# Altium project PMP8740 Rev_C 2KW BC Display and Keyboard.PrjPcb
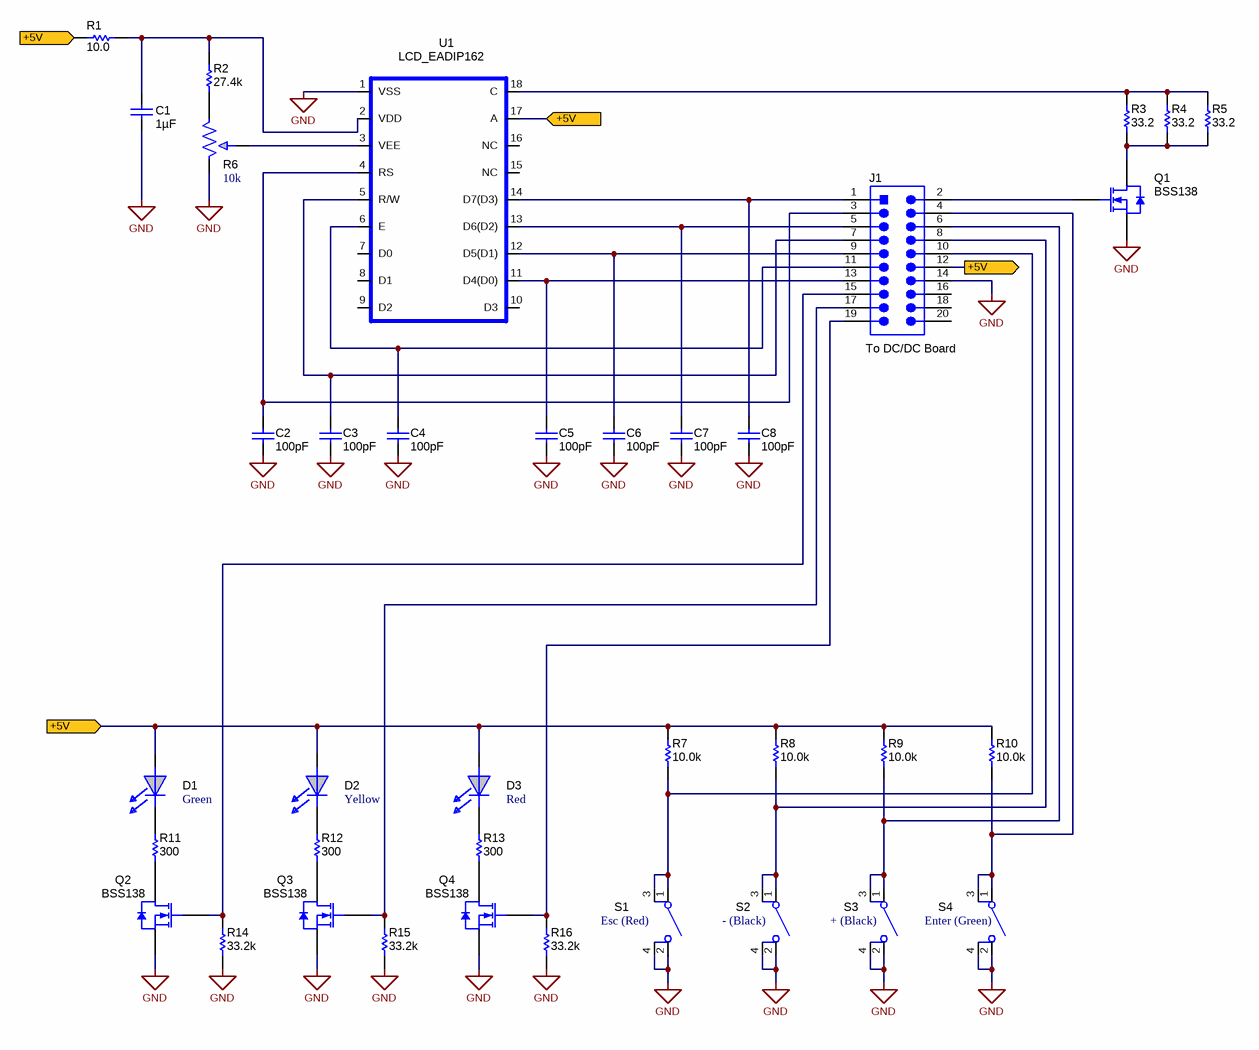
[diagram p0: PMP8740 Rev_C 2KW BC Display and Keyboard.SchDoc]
CopyrightYear: 2013; PCB_Layout: R. Scibilia; PCB_Rev: A; PRJ_Customer: Public Release; PRJ_Engineer: R. Scibilia; PRJ_Number: PMP8740; PRJ_Title: 1.44KW Battery Charger; SCH_Rev: A; TechSupport: http://www.ti.com/support
1 sheet, 37 parts. Net scope: flat (ports and power ports of the same name join across sheets).
Board file: PMP8740 Rev_C 2KW BC Display and Keyboard PCB.PcbDoc

## Sheet PMP8740 Rev_C 2KW BC Display and Keyboard.SchDoc: LCD Display
size 431 x 279 mm; Date: Not shown in title block; ApprovedBy: Not shown in title block; CheckedBy: Not shown in title block; Author: Not shown in title block; CompanyName: Not shown in title block; DrawnBy: R. Scibilia; Engineer: Not shown in title block; Organization: Not shown in title block; Address1: Not shown in title block; Address2: Not shown in title block; Address3: Not shown in title block; Address4: Not shown in title block; DocumentNumber: 1; Revision: Use project parameter SCH_Rev; SheetNumber: 1; SheetTotal: 1; PageSetup: Record=PageOptions|CenterHorizontal=True|CenterVertical=True|PrintScale=1.00|XCorrection=1.00|YCorrection=1.00|PrintKind=0|BorderSize=5000000|LeftOffset=0|BottomOffset=0|Orientation=2|PaperLength=1000|PaperWidth=1000|Scale=100|PaperSource=15|PrintQuality=600|MediaType=1|DitherType=10|PaperKind=Letter|PrintScaleMode=1

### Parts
C1  ValueDisplayed: 1µF  [0603]  (hidden comment: C1608X7R1E105K080AB)
C2  ValueDisplayed: 100pF  [0603]  (hidden comment: C1608C0G1H101J)
C3  ValueDisplayed: 100pF  [0603]  (hidden comment: C1608C0G1H101J)
C4  ValueDisplayed: 100pF  [0603]  (hidden comment: C1608C0G1H101J)
C5  ValueDisplayed: 100pF  [0603]  (hidden comment: C1608C0G1H101J)
C6  ValueDisplayed: 100pF  [0603]  (hidden comment: C1608C0G1H101J)
C7  ValueDisplayed: 100pF  [0603]  (hidden comment: C1608C0G1H101J)
C8  ValueDisplayed: 100pF  [0603]  (hidden comment: C1608C0G1H101J)
D1  value Green  [D_LED_T1-3/4]  (hidden comment: D_LED_HLMP-ED80)
D2  value Yellow  [D_LED_T1-3/4]  (hidden comment: D_LED_HLMP-ED80)
D3  value Red  [D_LED_T1-3/4]  (hidden comment: D_LED_HLMP-ED80)
J1  66506-072LF  [CONN_66506-072LF]  (value not drawn)
Q1  BSS138  [SOT-23]
Q2  BSS138  [SOT-23]
Q3  BSS138  [SOT-23]
Q4  BSS138  [SOT-23]
R1  value 10.0  [0603]  (hidden comment: CRCW060310R0FKEA)
R2  value 27.4k  [0603]  (hidden comment: CRCW060327K4FKEA)
R3  ValueDisplayed: 33.2  [1206]  (hidden comment: CRCW120633R2FKEA)
R4  ValueDisplayed: 33.2  [1206]  (hidden comment: CRCW120633R2FKEA)
R5  ValueDisplayed: 33.2  [1206]  (hidden comment: CRCW120633R2FKEA)
R6  value 10k  [POT-3361P]  (hidden comment: 3361P-1-103GLF)
R7  value 10.0k  [0603]  (hidden comment: CRCW060310K0FKEA)
R8  value 10.0k  [0603]  (hidden comment: CRCW060310K0FKEA)
R9  value 10.0k  [0603]  (hidden comment: CRCW060310K0FKEA)
R10  value 10.0k  [0603]  (hidden comment: CRCW060310K0FKEA)
R11  value 300  [0805_HV]  (hidden comment: ERJ-6GEYJ301V)
R12  value 300  [0805_HV]  (hidden comment: ERJ-6GEYJ301V)
R13  value 300  [0805_HV]  (hidden comment: ERJ-6GEYJ301V)
R14  ValueDisplayed: 33.2k  [0603]  (hidden comment: CRCW060333K2FKEA)
R15  ValueDisplayed: 33.2k  [0603]  (hidden comment: CRCW060333K2FKEA)
R16  ValueDisplayed: 33.2k  [0603]  (hidden comment: CRCW060333K2FKEA)
S1  value Esc (Red)  [SWITCH_95C]  (hidden comment: SW_95CW06XXGWT)
S2  value - (Black)  [SWITCH_95C]  (hidden comment: SW_95CW06XXGWT)
S3  value + (Black)  [SWITCH_95C]  (hidden comment: SW_95CW06XXGWT)
S4  value Enter (Green)  [SWITCH_95C]  (hidden comment: SW_95CW06XXGWT)
U1  LCD_EADIP162  [LCD_EADIP162]

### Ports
+5V

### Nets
GND: C1.2 C2.2 C3.2 C4.2 C5.2 C6.2 C7.2 C8.2 J1.14 Q1.2(S) Q2.2(S) Q3.2(S) Q4.2(S) R6.1 R14.1 R15.1 R16.1 S1.2 S1.4 S2.2 S2.4 S3.2 S3.4 S4.2 S4.4 U1.1(VSS)
+5V: D1.2(A) D2.2(A) D3.2(A) J1.12 R1.1 R7.2 R8.2 R9.2 R10.2 U1.17(A) ; port +5V
NetC1_1: C1.1 R1.2 R2.2 U1.2(VDD)
NetC2_1: C2.1 J1.3 U1.4(RS)
NetC3_1: C3.1 J1.7 U1.5(R/W)
NetC4_1: C4.1 J1.11 U1.6(E)
NetC5_1: C5.1 J1.13 U1.11(D4(D0))
NetC6_1: C6.1 J1.9 U1.12(D5(D1))
NetC7_1: C7.1 J1.5 U1.13(D6(D2))
NetC8_1: C8.1 J1.1 U1.14(D7(D3))
NetD1_1: D1.1(C) R11.1
NetD2_1: D2.1(C) R12.1
NetD3_1: D3.1(C) R13.1
NetJ1_2: J1.2 Q1.1(G)
NetJ1_4: J1.4 R10.1 S4.1 S4.3
NetJ1_6: J1.6 R9.1 S3.1 S3.3
NetJ1_8: J1.8 R8.1 S2.1 S2.3
NetJ1_10: J1.10 R7.1 S1.1 S1.3
NetJ1_15: J1.15 Q2.1(G) R14.2
NetJ1_17: J1.17 Q3.1(G) R15.2
NetJ1_19: J1.19 Q4.1(G) R16.2
NetQ1_3: Q1.3(D) R3.1 R4.1 R5.1
NetQ2_3: Q2.3(D) R11.2
NetQ3_3: Q3.3(D) R12.2
NetQ4_3: Q4.3(D) R13.2
NetR2_1: R2.1 R6.3
NetR3_2: R3.2 R4.2 R5.2 U1.18(C)
NetR6_2: R6.2 U1.3(VEE)

Not connected (* = marked no-connect by the designer): J1 16 18 20; U1 7(D0) 8(D1) 9(D2) 10(D3) 15(NC) 16(NC)

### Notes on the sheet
- (near J1) To DC/DC Board

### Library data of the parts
C1 = C1608X7R1E105K080AB: CAP, CERM, 1uF, 25V, +/-10%, X7R, 0603; Manufacturer: TDK; Polarized: N; CompType: Capacitor; U/M: EA; Cap_F: 0.000001; Tolerance_%: 10; Value1: Unknown; VDC_V: 25; TaMin_C: -55; TaMax_C: 125
C2-C8 = C1608C0G1H101J: CAP, CERM, 100 pF, 50 V, +/- 5%, C0G/NP0, 0603; Manufacturer: TDK; Polarized: N; CompType: Capacitor; Value: 100pF; U/M: EA; Cap_F: 0.0000000001; Tolerance_%: 5; ESR_ohm: 0.1679; Value1: 0.1679 ohm; VDC_V: 50; Value2: 50V; TaMin_C: -55; TaMax_C: 125
D1 = D_LED_HLMP-ED80: LED 5MM GREEN DIFFUSED; Manufacturer: Lite-On; Area: 61100
D2 = D_LED_HLMP-ED80: LED 5MM YELLOW DIFFUSED; Manufacturer: Lite-On; Area: 61100
D3 = D_LED_HLMP-ED80: LED 5MM RED DIFFUSED; Manufacturer: Lite-On; Area: 61100
J1 = 66506-072LF: Header (shrouded), 100mil, 10x2, Gold plated, TH; Manufacturer: FCI; SymbolCreator: a0412235; Note: Need STEP model; U/M: EA
Q1-Q4 = BSS138: MOSFET, N-CH, 50V, 0.22A, SOT-23; Manufacturer: Fairchild Semiconductor; Alternate Manufacturer: None; U/M: EA; ChType: N; VdsMax_V: 50; Value1: 6 ohm; Rdson45_Ohm: 6; Value2: 1.7 nC; QgTyp_nC: 1.7; Vgs_V: 20; IdsMax_A: 0.22
R1 = CRCW060310R0FKEA: RES, 10.0 ohm, 1%, 0.1W, 0603; Manufacturer: Vishay-Dale; CompType: Resistor; Res_ohm: 10; Value_Code: 10R0; Tolerance_%: 1; Power_W: 0.1; VDC_V: 75; TempCo: 100 ppm/C; EIA_Code: E96; U/M: EA
R2 = CRCW060327K4FKEA: RES, 27.4k ohm, 1%, 0.1W, 0603; Manufacturer: Vishay-Dale; CompType: Resistor; Res_ohm: 27400; Value_Code: 27k4; Tolerance_%: 1; Power_W: 0.1; VDC_V: 75; TempCo: 100 ppm/C; EIA_Code: E96; U/M: EA
R3-R5 = CRCW120633R2FKEA: RES, 33.2, 1%, 0.25 W, 1206; Manufacturer: Vishay-Dale; CompType: Resistor; Value: 33.2; Value_Code: 33R2; Tolerance_%: 1; Power_W: 0.25; Value2: 0.25W; VDC_V: 200; TempCo: 100 ppm/C; EIA_Code: E96; U/M: EA
R6 = POT_3361P_SERIES: Potentiometer, SMT 1/4 Square; Manufacturer: Bourns; Area: 83.20 mm
R7-R10 = CRCW060310K0FKEA: RES, 10.0k ohm, 1%, 0.1W, 0603; Manufacturer: Vishay-Dale; CompType: Resistor; Res_ohm: 10000; Value_Code: 10k0; Tolerance_%: 1; Power_W: 0.1; VDC_V: 75; TempCo: 100 ppm/C; EIA_Code: E96; U/M: EA
R11-R13 = ERJ-6GEYJ301V: RES, 300 ohm, 5%, 0.125W, 0805; Manufacturer: Panasonic; CompType: Resistor; Value_Code: 300R; Tolerance_%: 5; Power_W: 0.125; VDC_V: 150; TempCo: 200 ppm/C; EIA_Code: E24; U/M: EA
R14-R16 = CRCW060333K2FKEA: RES, 33.2 k, 1%, 0.1 W, 0603; Manufacturer: Vishay-Dale; CompType: Resistor; Value: 33.2k; Res_ohm: 33200; Value_Code: 33k2; Tolerance_%: 1; Power_W: 0.1; Value2: 0.1W; VDC_V: 75; TempCo: 100 ppm/C; EIA_Code: E96; U/M: EA
S1 = SW_95CW06XXGWT: SWITCH PUSH SPST-NO 0.01A 35V; Manufacturer: E-Switch; PartNumber: KS-01Q-02
S2 S3 = SW_95CW06XXGWT: SWITCH PUSH SPST-NO 0.01A 35V; Manufacturer: E-Switch; PartNumber: KS-01Q-01
S4 = SW_95CW06XXGWT: SWITCH PUSH SPST-NO 0.01A 35V; Manufacturer: E-Switch; PartNumber: KS-01Q-03
U1 = LCD_EADIP162: LCD, MODULE 2x16 - 6.68mm; PartNumber: EADIP162-xxx; Manufacturer: Electronic Assembly; Area: 2030 mm

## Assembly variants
001: not fitted FID1 FID2 FID3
